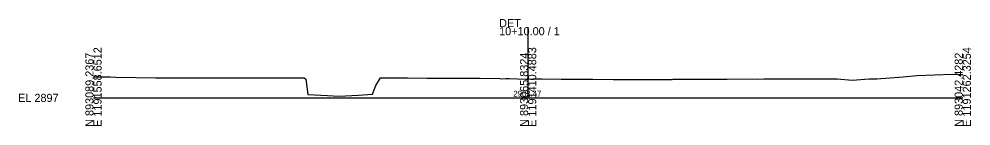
# Model space of a CAD drawing. Extents: x -26 to 1303, y -10 to 9537.
# Drawn here: x -25.7 to 302.8, y 490.3 to 527.2 of the extents above; entities that cross this region are included whole.
import ezdxf

# ---------------------------------------------------------------- set-up
doc = ezdxf.new("R2010")
doc.units = 0
for name, color, linetype in [('Default', 7, 'Continuous'), ('Exist Cross Section Cell', 7, 'Continuous'), ('Exist XS Center Line Elevation Label', 7, 'Continuous'), ('Exist XS Ground Line', 7, 'Continuous')]:
    doc.layers.add(name, color=color, linetype=linetype)

msp = doc.modelspace()

# ---------------------------------------------------------------- linework, layer by layer
at = {"layer": 'Exist Cross Section Cell'}
for p, q in [((150, 500), (150, 524.4)), ((0, 500), (150, 500)), ((150, 500), (300, 500))]:
    msp.add_line(p, q, dxfattribs=at)
at = {"layer": 'Exist XS Ground Line'}
for p, q in [((0, 507.31), (4.44, 507.23)), ((4.44, 507.23), (5.72, 507.22)), ((5.72, 507.22), (7.77, 507.19)), ((7.77, 507.19), (21.42, 506.97)), ((21.42, 506.97), (26.4, 506.91)), ((26.4, 506.91), (26.97, 506.9)), ((26.97, 506.9), (34.34, 506.9)), ((34.34, 506.9), (36.97, 506.89)), ((36.97, 506.89), (45.78, 506.89)), ((45.78, 506.89), (46.97, 506.89)), ((46.97, 506.89), (54.95, 506.9)), ((54.95, 506.9), (56.99, 506.9)), ((56.99, 506.9), (65.76, 506.92)), ((65.76, 506.92), (67.06, 506.93)), ((67.06, 506.93), (72.37, 506.91)), ((72.37, 506.91), (72.75, 506.91)), ((72.75, 506.91), (73.31, 506.5)), ((73.31, 506.5), (73.95, 501.16)), ((97.49, 504.22), (98.71, 506.34)), ((98.71, 506.34), (99.05, 506.91)), ((99.05, 506.91), (101.72, 506.9)), ((101.72, 506.9), (104.92, 506.88)), ((104.92, 506.88), (108.34, 506.88)), ((108.34, 506.88), (115.06, 506.85)), ((115.06, 506.85), (116.91, 506.85)), ((116.91, 506.85), (122.7, 506.82)), ((122.7, 506.82), (124.32, 506.82)), ((124.32, 506.82), (132.8, 506.77)), ((132.8, 506.77), (133.48, 506.77)), ((133.48, 506.77), (140.25, 506.72)), ((140.25, 506.72), (140.76, 506.61)), ((140.76, 506.61), (142.33, 506.66)), ((142.33, 506.66), (142.86, 506.69)), ((142.86, 506.69), (143.46, 506.67)), ((143.46, 506.67), (149.17, 506.45)), ((149.17, 506.45), (150, 506.47)), ((150, 506.47), (151.77, 506.55)), ((151.77, 506.55), (152.76, 506.55)), ((152.76, 506.55), (154.8, 506.53)), ((154.8, 506.53), (161.43, 506.45)), ((161.43, 506.45), (166.48, 506.42)), ((166.48, 506.42), (169.09, 506.41)), ((169.09, 506.41), (172.31, 506.41)), ((172.31, 506.41), (179.31, 506.36)), ((179.31, 506.36), (180.45, 506.36)), ((180.45, 506.36), (184.8, 506.32)), ((184.8, 506.32), (189.28, 506.33)), ((189.28, 506.33), (189.68, 506.34)), ((189.68, 506.34), (199.74, 506.38)), ((199.74, 506.38), (200.06, 506.41)), ((200.06, 506.41), (209.62, 506.47)), ((209.62, 506.47), (218.69, 506.5)), ((218.69, 506.5), (227.48, 506.53)), ((227.48, 506.53), (228.7, 506.45)), ((228.7, 506.45), (231.36, 506.56)), ((231.36, 506.56), (240.05, 506.58)), ((240.05, 506.58), (243.29, 506.52)), ((243.29, 506.52), (250.25, 506.54)), ((250.25, 506.54), (256.72, 506.55)), ((256.72, 506.55), (261.85, 506.12)), ((261.85, 506.12), (267.66, 506.55)), ((267.66, 506.55), (269.38, 506.55)), ((269.38, 506.55), (269.9, 506.55)), ((269.9, 506.55), (270.37, 506.58)), ((270.37, 506.58), (271.76, 506.67)), ((271.76, 506.67), (274.98, 506.89)), ((274.98, 506.89), (279.46, 507.31)), ((279.46, 507.31), (284.14, 507.77)), ((284.14, 507.77), (296.37, 508.13)), ((296.37, 508.13), (298.53, 508.06)), ((298.53, 508.06), (300, 508.07)), ((96.3, 501.27), (97.49, 504.22)), ((73.95, 501.16), (80.81, 500.82)), ((80.81, 500.82), (84.71, 500.57)), ((84.71, 500.57), (91.49, 500.99)), ((91.49, 500.99), (96.3, 501.27))]:
    msp.add_line(p, q, dxfattribs=at)

# ---------------------------------------------------------------- texts
at = {"layer": 'Default'}
msp.add_text('-', height=0.0001, dxfattribs=at).set_placement((0, 500))
at = {"layer": 'Exist Cross Section Cell'}
for s, p in [('DET', (140, 524.4)), ('10+10.00 / 1', (140, 521.6)), ('EL 2897', (-26, 498.6))]:
    msp.add_text(s, height=2.8, dxfattribs=at).set_placement(p)
for s, p in [('E 1191558.6512', (2.8, 490)), ('E 1191410.4883', (152.8, 490)), ('E 1191262.3254', (302.8, 490)), ('N 893089.2367', (0, 490)), ('N 893065.8324', (150, 490)), ('N 893042.4282', (300, 490))]:
    msp.add_text(s, height=2.8, rotation=90, dxfattribs=at).set_placement(p)
at = {"layer": 'Exist XS Center Line Elevation Label'}
msp.add_text('2903.47', height=2, dxfattribs=at).set_placement((144.91, 500.47))

doc.saveas('drawing.dxf')
